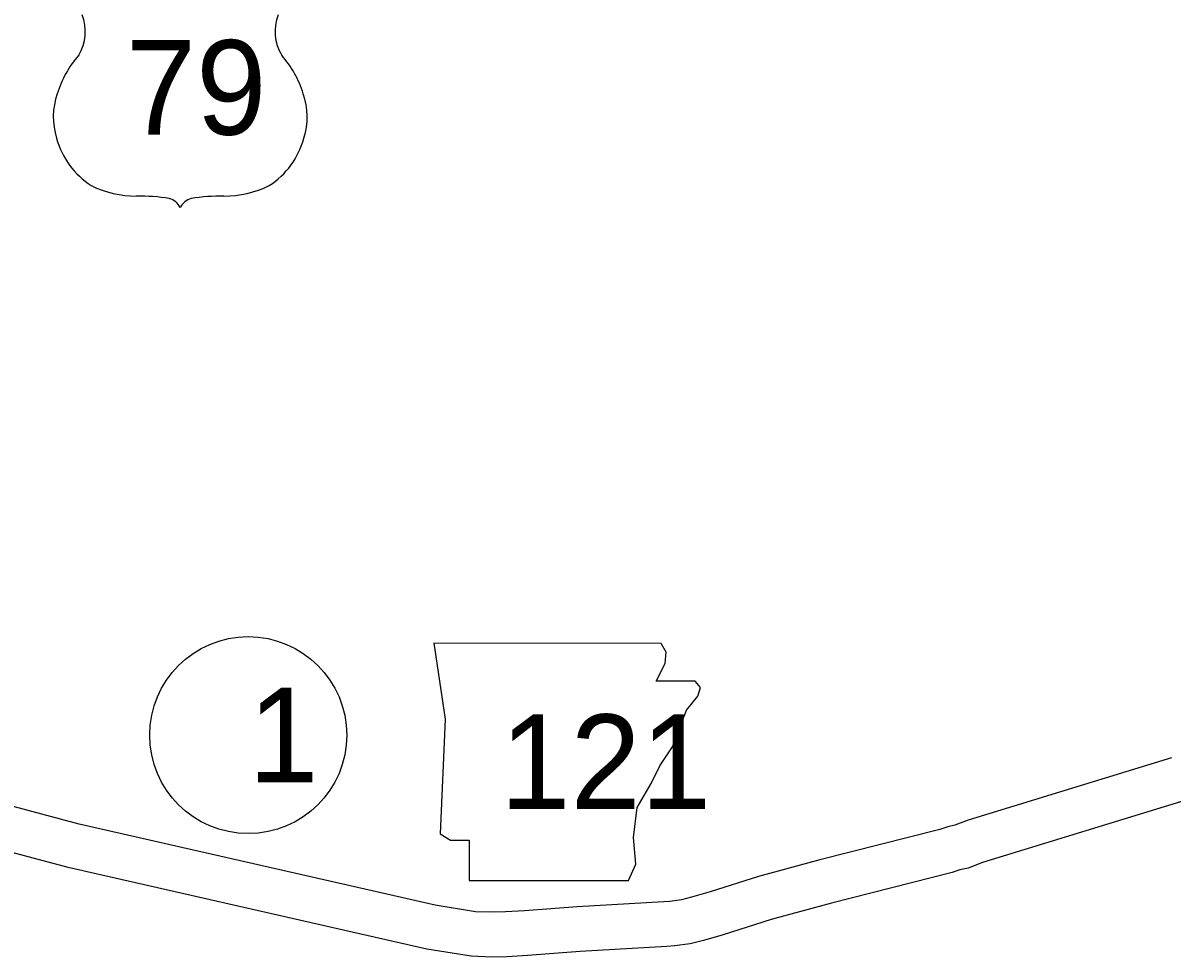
# Model space of a CAD drawing. Extents: x -939622 to -934222, y 1383701 to 1385301.
# Drawn here: x -935735.82 to -935712.73, y 1384189.37 to 1384208.15 of the extents above; entities that cross this region are included whole.
import ezdxf

# ---------------------------------------------------------------- set-up
doc = ezdxf.new("R2010")
doc.units = 0
for name, color, linetype in [('Level 10', 7, 'Continuous'), ('Level 21', 7, 'Continuous'), ('Level 22', 7, 'Continuous'), ('Level 27', 7, 'Continuous')]:
    doc.layers.add(name, color=color, linetype=linetype)

msp = doc.modelspace()

# ---------------------------------------------------------------- linework, layer by layer
at = {"layer": 'Level 10'}
for points in [[(-935712.739, 1384193.378), (-935716.826, 1384192.123), (-935717.096, 1384192.023), (-935717.239, 1384191.988), (-935717.398, 1384191.937), (-935719.808, 1384191.326), (-935721.044, 1384190.987), (-935722.013, 1384190.68), (-935722.388, 1384190.572), (-935722.587, 1384190.519), (-935722.823, 1384190.489), (-935722.942, 1384190.48), (-935724.684, 1384190.378), (-935725.745, 1384190.3), (-935726.128, 1384190.277), (-935726.402, 1384190.271), (-935726.73, 1384190.283), (-935727.537, 1384190.412), (-935734.698, 1384192.043), (-935737.331, 1384192.749)], [(-935712.475, 1384192.518), (-935716.537, 1384191.271), (-935716.83, 1384191.161), (-935716.996, 1384191.121), (-935717.151, 1384191.071), (-935719.578, 1384190.456), (-935720.789, 1384190.124), (-935721.752, 1384189.818), (-935722.149, 1384189.704), (-935722.414, 1384189.634), (-935722.732, 1384189.593), (-935722.882, 1384189.582), (-935724.625, 1384189.48), (-935725.685, 1384189.402), (-935726.091, 1384189.377), (-935726.409, 1384189.371), (-935726.818, 1384189.385), (-935727.708, 1384189.528), (-935734.915, 1384191.169), (-935737.558, 1384191.878)]]:
    msp.add_lwpolyline(points, dxfattribs=at)
at = {"layer": 'Level 21'}
msp.add_lwpolyline([(-935727.565, 1384195.68), (-935727.337, 1384194.157), (-935727.438, 1384191.848), (-935727.235, 1384191.721), (-935726.854, 1384191.721), (-935726.854, 1384190.909), (-935723.657, 1384190.909), (-935723.505, 1384191.239), (-935723.555, 1384191.772), (-935723.479, 1384192.381), (-935723.2, 1384192.863), (-935723.023, 1384193.218), (-935722.769, 1384193.599), (-935722.617, 1384194.005), (-935722.49, 1384194.335), (-935722.261, 1384194.614), (-935722.211, 1384194.792), (-935722.312, 1384194.919), (-935723.099, 1384194.919), (-935722.921, 1384195.274), (-935722.896, 1384195.502), (-935723.001, 1384195.678)], close=True, dxfattribs=at)
at = {"layer": 'Level 22'}
for centre, radius, start, end in [((-935735.496, 1384207.983), 0.925, 328.8105, 21.2108), ((-935729.833, 1384207.983), 0.925, 158.7892, 211.1895), ((-935733.077, 1384206.088), 2.157, 138.9565, 162.6913), ((-935732.251, 1384206.088), 2.157, 17.3087, 41.0435), ((-935733.789, 1384206.264), 1.426, 160.9576, 197.3819), ((-935731.539, 1384206.264), 1.426, 342.6181, 19.0424), ((-935733.557, 1384206.268), 1.65, 195.1074, 237.1312), ((-935731.771, 1384206.268), 1.65, 302.8688, 344.8926), ((-935733.527, 1384206.788), 2.118, 244.0771, 269.5779), ((-935731.802, 1384206.788), 2.118, 270.4221, 295.9229), ((-935733.478, 1384200.79), 3.88, 81.1942, 90.9539), ((-935732.992, 1384204.269), 0.372, 28.0342, 72.9864), ((-935732.336, 1384204.269), 0.372, 107.0136, 151.9658), ((-935731.851, 1384200.79), 3.88, 89.0461, 98.8058)]:
    msp.add_arc(centre, radius, start, end, dxfattribs=at)
at = {"layer": 'Level 27'}
msp.add_circle((-935731.297, 1384193.833), 1.98, dxfattribs=at)

# ---------------------------------------------------------------- texts
at = {"layer": 'Level 21'}
msp.add_text('121', height=1.9008, dxfattribs=at).set_placement((-935726.234, 1384192.347))
at = {"layer": 'Level 22'}
msp.add_text('79', height=1.9008, dxfattribs=at).set_placement((-935733.757, 1384205.907))
at = {"layer": 'Level 27'}
msp.add_text('1', height=1.901, dxfattribs=at).set_placement((-935731.297, 1384192.883))

doc.saveas('drawing.dxf')
